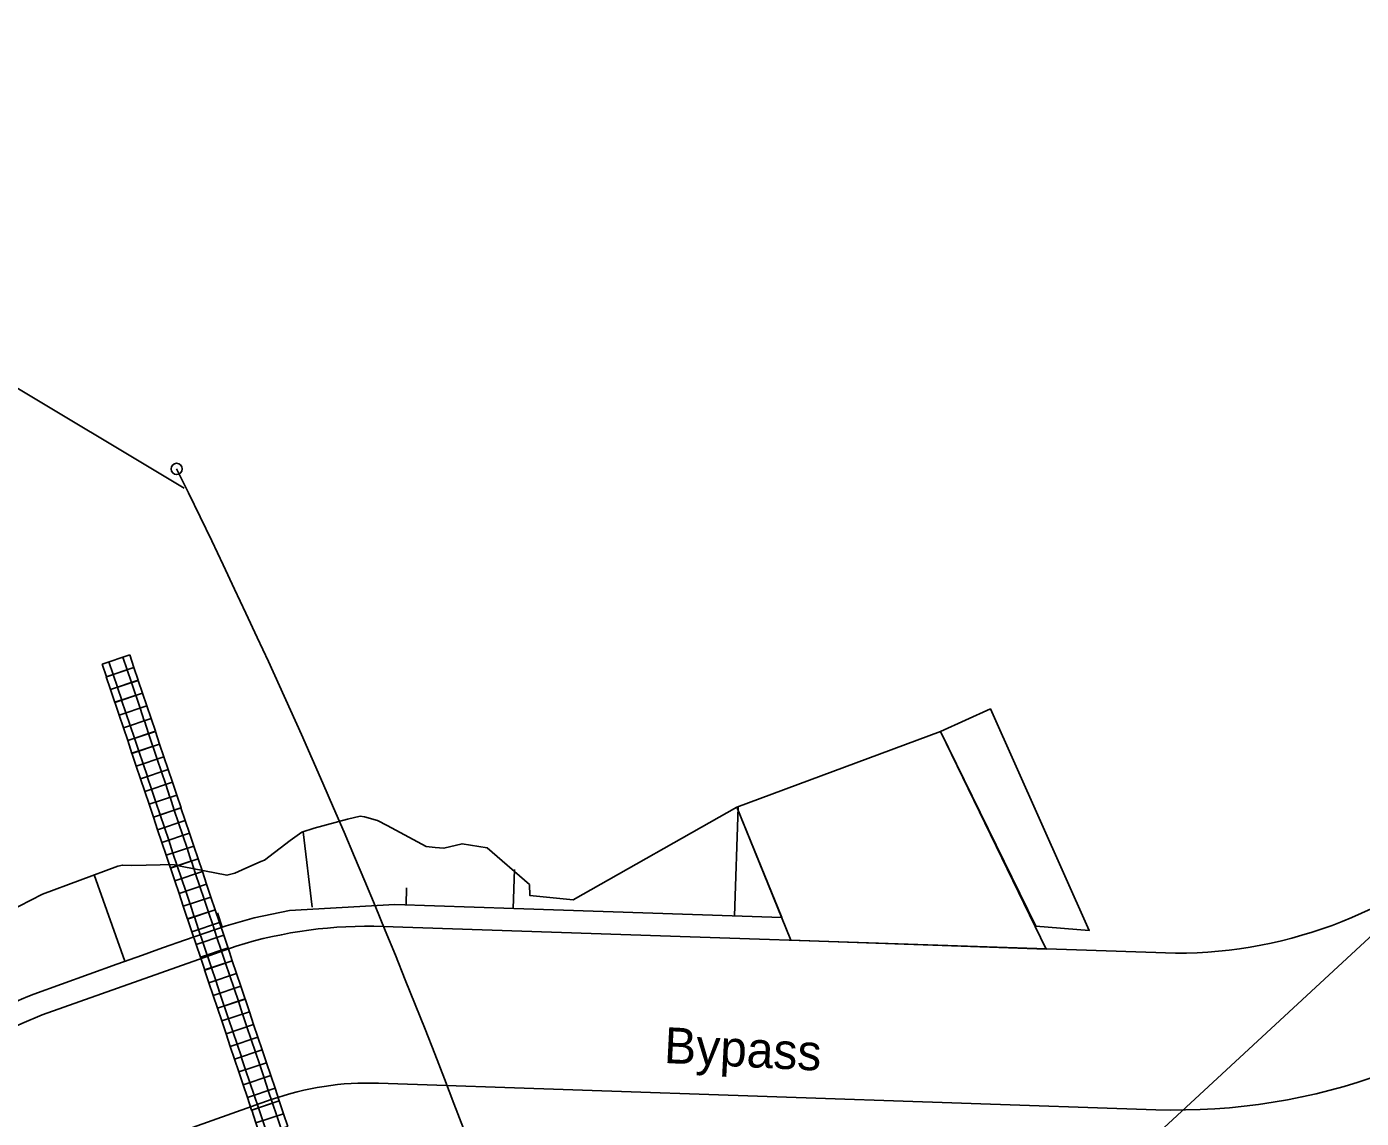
# Model space of a CAD drawing. Extents: x -526854 to -526702, y -1078757 to -1078333.
# Drawn here: x -526766.43 to -526736.67, y -1078457.38 to -1078433.01 of the extents above; entities that cross this region are included whole.
import ezdxf

# ---------------------------------------------------------------- set-up
doc = ezdxf.new("R2010")
doc.units = 0
for name, color, linetype in [('K-osa', 7, 'Continuous'), ('SO 01-10-01osa', 7, 'Continuous'), ('SO 01-11-01 žlabovky', 7, 'Continuous'), ('Vrstva 12', 7, 'Continuous')]:
    doc.layers.add(name, color=color, linetype=linetype)

# ---------------------------------------------------------------- blocks, each defined once
blk = doc.blocks.new('ureuuřu')
at = {"layer": 'SO 01-11-01 žlabovky'}
for p, q in [((-547430.299, -1195558.893), (-547430.55, -1195559.059)), ((-547430.299, -1195558.893), (-547429.941, -1195559.435)), ((-547430.55, -1195559.059), (-547430.191, -1195559.601)), ((-547430.212, -1195559.026), (-547430.462, -1195559.192)), ((-547430.028, -1195559.303), (-547430.279, -1195559.468)), ((-547429.941, -1195559.435), (-547430.191, -1195559.601))]:
    blk.add_line(p, q, dxfattribs=at)
blk = doc.blocks.new('ra')
for p, q in [((-526750.562, -1078450.43), (-526750.645, -1078452.86)), ((-526760.064, -1078452.662), (-526760.266, -1078450.981)), ((-526743.352, -1078459.695), (-526733.91, -1078450.954)), ((-526755.581, -1078452.691), (-526755.551, -1078451.826)), ((-526764.925, -1078451.94), (-526764.242, -1078453.871)), ((-526757.971, -1078452.609), (-526757.959, -1078452.231)), ((-526762.072, -1078453.107), (-526762.174, -1078452.793)), ((-526740.808, -1078453.691), (-526758.482, -1078453.092)), ((-526761.757, -1078453.531), (-526766.084, -1078455.069)), ((-526749.122, -1078453.411), (-526749.121, -1078453.411))]:
    blk.add_line(p, q)
for points in [[(-526746.051, -1078448.742), (-526744.938, -1078448.238), (-526742.732, -1078453.183), (-526743.923, -1078453.09), (-526746.051, -1078448.742)], [(-526749.59, -1078452.896), (-526750.59, -1078450.431), (-526754.243, -1078452.502), (-526755.21, -1078452.404), (-526755.218, -1078452.16), (-526756.165, -1078451.336), (-526756.721, -1078451.25), (-526757.125, -1078451.348), (-526757.324, -1078451.329), (-526757.524, -1078451.309), (-526758.392, -1078450.84), (-526758.609, -1078450.731), (-526758.895, -1078450.644), (-526758.991, -1078450.635), (-526759.276, -1078450.701), (-526760.022, -1078450.901), (-526760.296, -1078450.992), (-526760.554, -1078451.174), (-526761.126, -1078451.612), (-526761.21, -1078451.647), (-526761.628, -1078451.832), (-526761.793, -1078451.905), (-526761.965, -1078451.951), (-526762.961, -1078451.758), (-526763.132, -1078451.722), (-526763.242, -1078451.713), (-526763.456, -1078451.717), (-526763.768, -1078451.724), (-526764.084, -1078451.731), (-526764.299, -1078451.724), (-526764.397, -1078451.745), (-526766.083, -1078452.377), (-526766.857, -1078452.774)], [(-526766.27, -1078454.605), (-526764.419, -1078453.933), (-526763.853, -1078453.733), (-526763.57, -1078453.633), (-526763.382, -1078453.566), (-526762.91, -1078453.4), (-526761.982, -1078453.077), (-526761.36, -1078452.901), (-526760.57, -1078452.735), (-526758.218, -1078452.601), (-526755.57, -1078452.692), (-526749.59, -1078452.896)]]:
    blk.add_lwpolyline(points)
blk.add_lwpolyline([(-526749.391, -1078453.403), (-526750.59, -1078450.431), (-526746.052, -1078448.741), (-526743.694, -1078453.598)], close=True)
for centre, radius, start, end in [((-526740.788, -1078443.681), 10.01, 269.8845, 313.4032), ((-526758.808, -1078463.097), 10.01, 88.129, 107.1323), ((-526759.739, -1078470.839), 17.499, 111.9172, 127.4094), ((-526759.737, -1078470.84), 17, 111.9213, 164.1237)]:
    blk.add_arc(centre, radius, start, end)
at = {"layer": 'K-osa'}
for p, q in [((-526741.251, -1078457.183), (-526758.589, -1078456.591)), ((-526760.978, -1078456.959), (-526764.24, -1078458.113))]:
    blk.add_line(p, q, dxfattribs=at)
for centre, radius, start, end in [((-526740.789, -1078443.676), 13.515, 268.0422, 312.3982), ((-526758.811, -1078463.087), 6.5, 88.0422, 109.4821)]:
    blk.add_arc(centre, radius, start, end, dxfattribs=at)
blk.add_text('Bypass', height=0.8, rotation=357.1403).set_placement((-526752.229, -1078456.139))

msp = doc.modelspace()

# ---------------------------------------------------------------- linework, layer by layer
at = {"layer": 'SO 01-10-01osa'}
msp.add_circle((-526763.088, -1078442.883), 0.125, dxfattribs=at)
msp.add_arc((-526911.04, -1078515.926), 165, 359.90003, 26.27548, dxfattribs=at)
at = {"layer": 'Vrstva 12'}
msp.add_line((-526780.087, -1078433.014), (-526762.921, -1078443.313), dxfattribs=at)

# ---------------------------------------------------------------- block references
msp.add_blockref('ra', (0, 0))
at = {"layer": 'SO 01-11-01 žlabovky', "rotation": 75.01642015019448}
for p in [(-1540140.753, -240527.148), (-1540140.658, -240527.432), (-1540140.562, -240527.717), (-1540140.467, -240528.001), (-1540140.372, -240528.286), (-1540140.276, -240528.57), (-1540140.181, -240528.855), (-1540140.086, -240529.139), (-1540139.99, -240529.423), (-1540139.895, -240529.708), (-1540139.8, -240529.992), (-1540139.704, -240530.277), (-1540139.609, -240530.561), (-1540139.514, -240530.846), (-1540139.418, -240531.13), (-1540139.323, -240531.415), (-1540139.228, -240531.699), (-1540139.132, -240531.983), (-1540139.037, -240532.268), (-1540138.942, -240532.552), (-1540138.846, -240532.837), (-1540138.751, -240533.121), (-1540138.656, -240533.406), (-1540138.56, -240533.69), (-1540138.465, -240533.975), (-1540138.37, -240534.259), (-1540138.274, -240534.544), (-1540138.179, -240534.828), (-1540138.084, -240535.112), (-1540137.988, -240535.397), (-1540137.893, -240535.681), (-1540137.798, -240535.966), (-1540137.702, -240536.25), (-1540137.607, -240536.535), (-1540137.512, -240536.819), (-1540137.416, -240537.104), (-1540137.321, -240537.388)]:
    msp.add_blockref('ureuuřu', p, dxfattribs=at)

doc.saveas('drawing.dxf')
